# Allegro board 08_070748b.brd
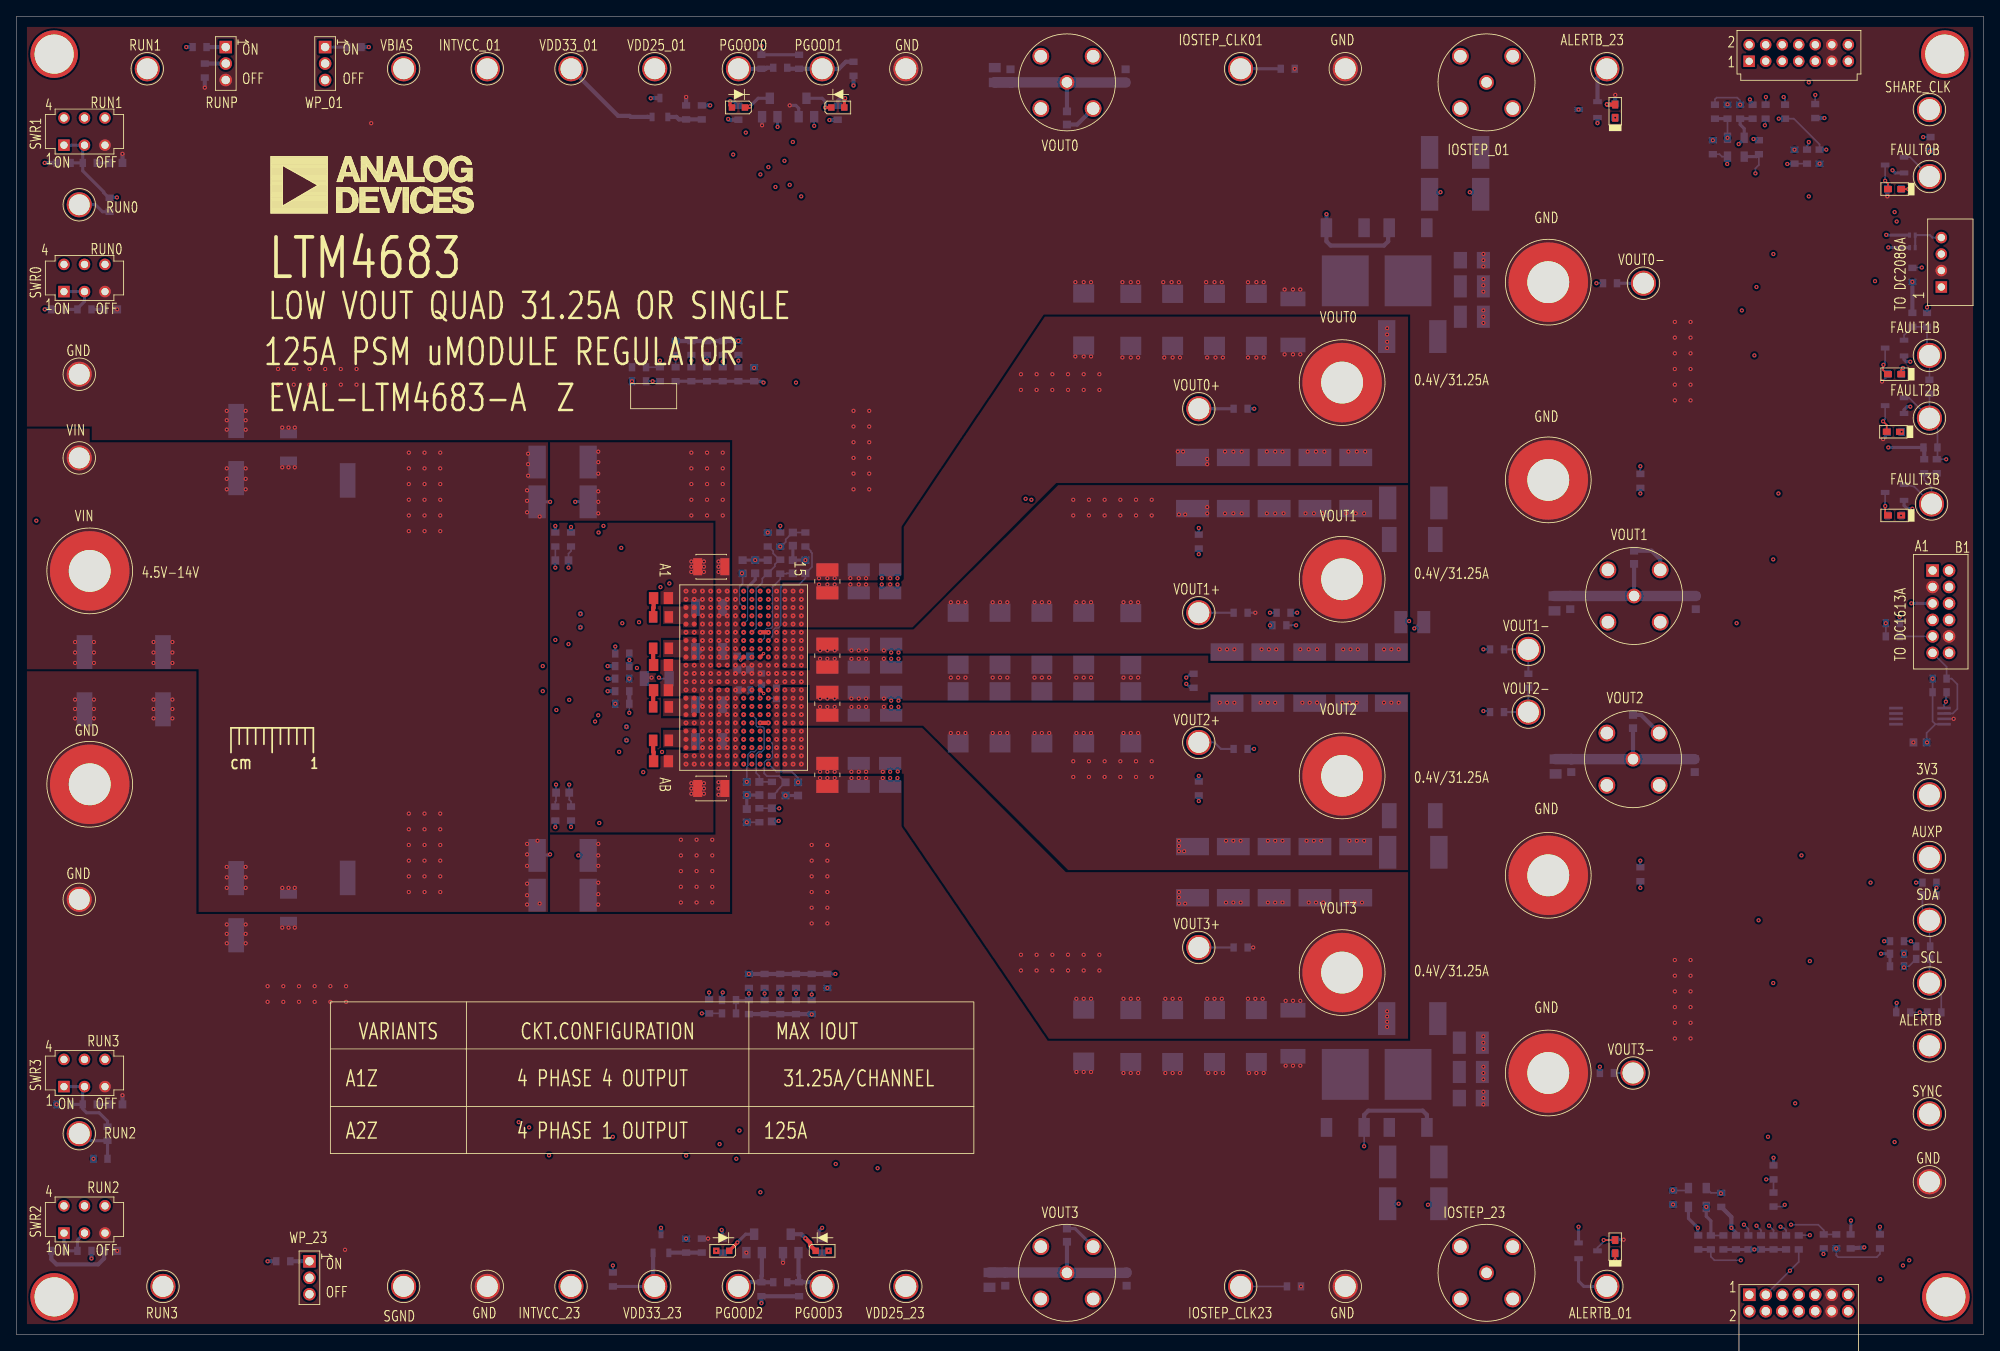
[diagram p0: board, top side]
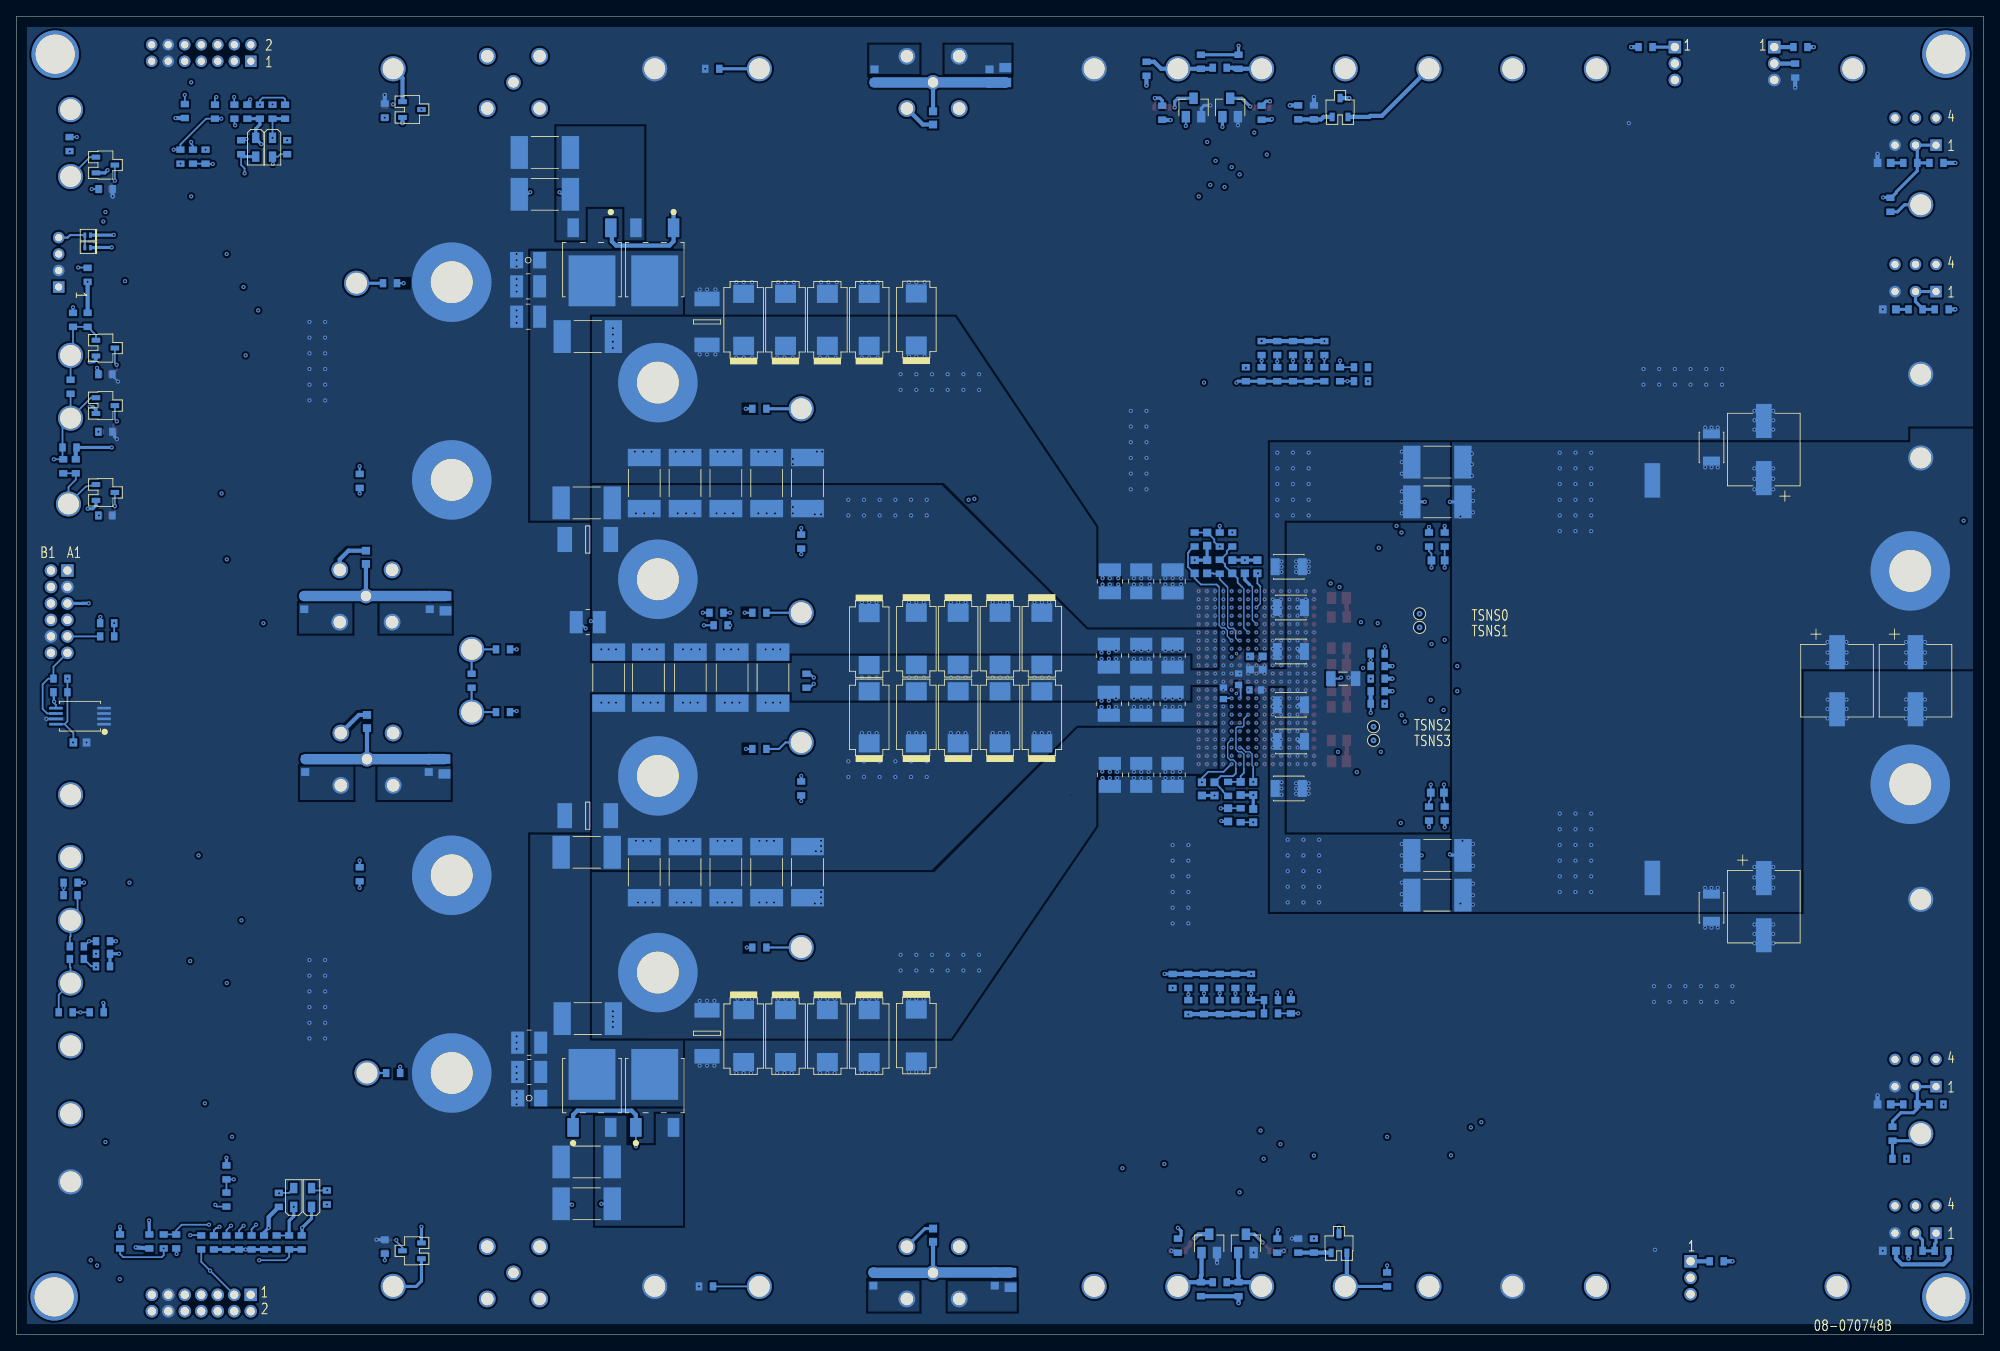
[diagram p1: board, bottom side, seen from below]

Outline 238.76 x 160.02 mm; copper layers: TOP, LAYER_2, LAYER_3, LAYER_4, LAYER_5, LAYER_6, LAYER_7, BOTTOM. Coordinates in mm from the lower left corner of the outline.
Outline path: 0,160.02 0,0 238.76,0 238.76,160.02 0,160.02

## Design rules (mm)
constraint set DEFAULT: min track width 0.203

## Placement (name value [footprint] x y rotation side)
C1  1000pF  [C0603#2]  88.65 62.99 270 bottom
C2  100pF  [C0603#2]  90.17 66.29 90 bottom
C12  TBD0805  [C0805]  78.23 69.6 180 top
C14  0.1uF  [C0603#2]  231.05 71.88 180 bottom
C17  TBD0805  [C0805]  78.23 78.23 180 top
C18  1000pF  [C0603#2]  91.69 63.09 90 bottom
C19  100pF  [C0603#2]  93.34 66.24 90 bottom
C25  1uF  [C0603]  88.39 78.26 0 bottom
C26  2.2uF  [C0603#2]  87.5 81.53 90 bottom
C27  2.2uF  [C0603]  92.26 77.85 270 bottom
C28  TBD0603  [C0603#2]  66.21 93.98 0 bottom
C33  TBD0603  [C0603#2]  66.29 65.79 0 bottom
C38  4.7uF  [C0603#2]  89.03 81.53 90 bottom
C39  1UF  [C0603#2]  89.66 93.22 270 bottom
C40  1UF  [C0603#2]  88.14 93.22 270 bottom
C41  4.7uF  [C0603]  90.42 79.56 270 bottom
C42  1UF  [C0603#2]  88.65 66.29 90 bottom
C43  1UF  [C0603#2]  94.87 66.24 90 bottom
C44  22uF  [C1206]  77.72 79.63 0 bottom
C48  1000pF  [C0603#2]  95.76 93.22 90 bottom
C49  100pF  [C0603#2]  94.23 93.22 90 bottom
C50  1000pF  [C0603#2]  94.23 96.57 270 bottom
C51  100pF  [C0603#2]  91.19 93.22 90 bottom
C55  TBD0805  [C0805]  78.23 89.41 180 top
C56  TBD0805  [C0805]  78.23 81.28 180 top
C65  100uF  [C1206H71]  176.66 130.43 180 bottom
C66  100uF  [C1206H71]  176.53 28.7 180 bottom
C67  100uF  [C1210-2]  176.66 123.57 180 bottom
C68  100uF  [C1210-2]  176.53 35.43 180 bottom
C69  100uF  [C1210-2]  176.66 127.25 180 bottom
C70  100uF  [C1210-2]  176.53 31.88 180 bottom
C71  0.1uF  [C0603#2]  127.51 147.7 270 bottom
C72  0.1uF  [C0603#2]  196.34 94.36 90 bottom
C73  0.1uF  [C0603#2]  196.22 74.42 90 bottom
C74  0.1uF  [C0603#2]  127.51 12.06 90 bottom
C75  0.1uF  [C0603#2]  134.62 152.81 90 bottom
C76  0.1uF  [C0603#2]  188.59 88.86 270 bottom
C77  0.1uF  [C0603#2]  203.71 69.09 270 bottom
C78  0.1uF  [C0603#2]  134.75 6.73 270 bottom
C79  0.1uF  [C0603#2]  120.65 152.81 90 bottom
C80  0.1uF  [C0603#2]  203.83 88.86 270 bottom
C81  0.1uF  [C0603#2]  188.72 69.09 270 bottom
C82  0.1uF  [C0603#2]  120.02 6.73 270 bottom
C84  0.1uF  [C0805]  118.75 152.91 270 bottom
C85  0.1uF  [C0805]  186.69 88.76 90 bottom
C86  0.1uF  [C0805]  186.82 68.96 90 bottom
C87  0.1uF  [C0805]  118.11 6.63 90 bottom
C88  0.01uF  [C0603#2]  11.43 124.46 180 bottom
C89  0.01uF  [C0603#2]  12.06 142.24 180 bottom
C90  0.01uF  [C0603#2]  11.43 10.16 180 bottom
C91  0.01uF  [C0603#2]  12.06 27.94 180 bottom
CIN1  180UF  [CPLSMSQ327H472]  8.25 79.38 270 bottom
CIN2  180UF  [CPLSMSQ327H472]  17.78 79.38 270 bottom
CIN3  180UF  [CPLSMSQ327H472]  26.67 107.44 90 bottom
CIN4  180UF  [CPLSMSQ327H472]  26.67 51.94 270 bottom
CIN5  22uF  [C1210H106]  33.02 107.7 270 bottom
CIN6  22uF  [C1210H106]  33.02 51.82 90 bottom
CIN7  22uF  [C1210H106]  84.33 93.22 0 top
CIN8  22uF  [C1210H106]  84.33 93.22 0 bottom
CIN9  22uF  [C1210H106]  84.07 82.93 0 bottom
CIN10  22uF  [C1210H106]  84.07 88.27 0 bottom
CIN11  22uF  [C1210H106]  84.33 66.29 0 top
CIN12  22uF  [C1210H106]  84.33 66.29 0 bottom
CIN13  22uF  [C1210H106]  84.07 76.45 0 bottom
CIN14  22uF  [C1210H106]  84.07 72.01 0 bottom
CO1  100uF  [C1210-2]  98.42 91.44 270 top
CO2  100uF  [C1210-2]  106.05 91.44 270 bottom
CO3  100uF  [C1210-2]  102.23 91.44 270 bottom
CO4  100uF  [C1210-2]  98.42 91.44 270 bottom
CO5  680UF  [C7343H157]  150.5 123.19 90 bottom
CO6  680UF  [C7343H157]  145.41 123.19 90 bottom
CO7  680UF  [C7343H157]  140.34 123.19 90 bottom
CO8  680UF  [C7343H157]  135.25 123.19 90 bottom
CO9  680UF  [C7343H157]  129.54 123.23 90 bottom
CO10  100uF  [C1210-2]  106.17 82.42 90 bottom
CO11  100uF  [C1210-2]  102.23 82.42 90 bottom
CO12  100uF  [C1210-2]  98.42 82.42 90 top
CO13  100uF  [C1210-2]  98.42 82.42 90 bottom
CO14  680UF  [C7343H157]  114.3 84.47 270 bottom
CO15  680UF  [C7343H157]  119.38 84.47 270 bottom
CO16  680UF  [C7343H157]  124.46 84.47 270 bottom
CO17  680UF  [C7343H157]  129.54 84.47 270 bottom
CO18  680UF  [C7343H157]  135.25 84.43 270 bottom
CO19  100uF  [C1210-2]  98.42 76.58 270 top
CO20  100uF  [C1210-2]  106.17 76.58 270 bottom
CO21  100uF  [C1210-2]  102.23 76.58 270 bottom
CO22  100uF  [C1210-2]  98.42 76.58 270 bottom
CO23  680UF  [C7343H157]  114.3 74.93 90 bottom
CO24  680UF  [C7343H157]  119.38 74.93 90 bottom
CO25  680UF  [C7343H157]  124.46 74.93 90 bottom
CO26  680UF  [C7343H157]  129.54 74.93 90 bottom
CO27  680UF  [C7343H157]  135.25 74.93 90 bottom
CO28  100uF  [C1210-2]  98.42 67.94 90 top
CO29  100uF  [C1210-2]  106.05 67.94 90 bottom
CO30  100uF  [C1210-2]  102.23 67.94 90 bottom
CO31  100uF  [C1210-2]  98.42 67.94 90 bottom
CO32  680UF  [C7343H157]  150.5 36.24 270 bottom
CO33  680UF  [C7343H157]  145.41 36.24 270 bottom
CO34  680UF  [C7343H157]  140.34 36.24 270 bottom
CO35  680UF  [C7343H157]  135.25 36.24 270 bottom
CO36  680UF  [C7343H157]  129.54 36.3 270 bottom
CO37  100uF  [C1210-2]  169.42 86.49 180 bottom
D1  PMEG2005AEL,315  [SOD882]  230.12 133.48 0 bottom
D2  PMEG2005AEL,315  [SOD882]  230.12 131.95 0 bottom
D3  BAV16WS-7-F  [SOD323]  207.68 144.14 270 bottom
D4  BAV16WS-7-F  [SOD323]  209.72 144.14 270 bottom
D5  BAV16WS-7-F  [SOD323]  205.11 16.64 90 bottom
D6  BAV16WS-7-F  [SOD323]  202.95 16.64 90 bottom
DS1  150060GS75000  [LED0603-2]  87.63 148.97 180 top
DS3  150060GS75000  [LED0603-2]  99.69 148.97 0 top
DS4  TLMS1100-GS08  [LED0603]  194.06 148.53 90 top
DS5  150060GS75000  [LED0603-2]  85.72 10.16 180 top
DS6  TLMS1100-GS08  [LED0603]  227.96 139.06 180 top
DS7  150060GS75000  [LED0603-2]  97.79 10.16 0 top
DS8  TLMS1100-GS08  [LED0603]  227.96 116.59 180 top
DS9  TLMS1100-GS08  [LED0603]  194.06 10.67 90 top
DS10  TLMS1100-GS08  [LED0603]  227.81 109.6 180 top
DS11  TLMS1100-GS08  [LED0603]  227.96 99.44 180 top
J1  112404  [CNAMPHENOL112404]  178.44 152.02 0 top
J2  112404  [CNAMPHENOL112404]  178.44 7.49 0 top
J3  112404  [CNAMPHENOL112404]  127.51 152.02 0 top
J4  112404  [CNAMPHENOL112404]  196.34 89.66 0 top
J5  112404  [CNAMPHENOL112404]  196.22 69.85 0 top
J6  112404  [CNAMPHENOL112404]  127.51 7.49 0 top
NOREF  -  []  -215.26 133.35 0 top
NOREF#2  -  [unnamed#2]  234.19 4.57 0 top
NOREF#3  -  []  15.24 301.62 0 top
NOREF#4  -  []  238.76 0 90 top
NOREF#5  -  []  198.75 8.89 270 top
NOREF#6  -  []  0 0 90 top
NOREF#7  -  []  0 0 0 top
NOREF#8  -  []  -222.25 -146.05 0 top
NOREF#9  -  []  9.53 196.6 0 top
NOREF#10  -  []  78.11 197.23 0 top
NOREF#11  -  []  -66.04 -72.39 0 top
NOREF#12  -  []  30.86 130.05 0 top
NOREF#13  -  []  0 160.02 270 top
NOREF#14  -  []  116.84 181.36 0 top
NOREF#15  -  []  -222.25 -146.05 0 top
NOREF#16  -  []  76.2 344.8 0 top
NOREF#17  -  []  141.61 329.56 0 top
NOREF#18  -  [unnamed#2]  4.57 4.57 0 top
NOREF#19  -  [unnamed#2]  234.06 155.45 0 top
NOREF#20  -  []  116.2 199.14 0 top
NOREF#21  -  [unnamed#2]  4.57 155.45 0 top
NOREF#22  -  []  -242.44 -168.4 0 top
NOREF#23  -  []  348.62 318.77 0 top
NOREF#24  -  []  0 160.02 0 top
NOREF#25  -  []  132.72 8.89 0 top
NOREF#26  -  []  238.76 160.02 270 bottom
P1  NRPN031PAEN-RC  [CNTHMHDR1X3L326W79H235]  25.4 156.3 270 top
P2  NRPN031PAEN-RC  [CNTHMHDR1X3L326W79H235]  37.47 156.3 270 top
P3  98414-G06-12ULF  [CNTHMHDR2X6L528W240H244]  232.58 92.76 270 top
P4  NPPN072FJFN-RC  [CNTHFHDRRA2X7L571W283H197]  210.31 156.59 0 top
P5  0877601416  [CNMOLEX0877601416]  210.33 4.83 0 top
P6  DF3A-4P-2DSA  [CNTHMHDR1X4L394W197H209]  233.64 127.18 90 top
P7  5502-14-0034  [CNRDIS5502-14-0034]  74.04 73.79 180 bottom
P8  5502-14-0034  [CNRDIS5502-14-0034]  74.04 72.14 180 bottom
P9  5502-14-0034  [CNRDIS5502-14-0034]  68.45 85.85 180 bottom
P10  5502-14-0034  [CNRDIS5502-14-0034]  68.45 87.5 180 bottom
P17  NRPN031PAEN-RC  [CNTHMHDR1X3L326W79H235]  35.56 8.89 270 top
Q1  SUD50N04-8M8P-4GE3  [TO252-3]  161.29 130.18 0 bottom
Q2  SUD50N04-8M8P-4GE3  [TO252-3]  168.91 29.34 180 bottom
Q3  SUD50N04-8M8P-4GE3  [TO252-3]  168.91 130.18 0 bottom
Q4  SUD50N04-8M8P-4GE3  [TO252-3]  161.29 29.34 180 bottom
Q5  2N7002A-7  [SOT23]  91.44 148.97 180 bottom
Q7  SI2365EDS-T1-GE3  [SOT23_B]  78.11 148.97 180 bottom
Q8  2N7002A-7  [SOT23]  95.89 148.97 180 bottom
Q9  SI2365EDS-T1-GE3  [SOT23_B]  190.75 148.72 270 bottom
Q10  SI2365EDS-T1-GE3  [SOT23_B]  78.23 11.06 180 bottom
Q11  2N7002A-7  [SOT23]  89.53 11.06 180 bottom
Q12  SI2365EDS-T1-GE3  [SOT23_B]  227.96 141.99 270 bottom
Q13  2N7002A-7  [SOT23]  93.98 11.06 180 bottom
Q14  SI2365EDS-T1-GE3  [SOT23_B]  227.96 119.76 270 bottom
Q15  SI2365EDS-T1-GE3  [SOT23_B]  190.75 10.16 90 bottom
Q16  SI2365EDS-T1-GE3  [SOT23_B]  227.96 112.78 270 bottom
Q17  SI2365EDS-T1-GE3  [SOT23_B]  227.96 102.23 270 bottom
R1  10K  [R0603]  231.56 105.41 90 bottom
R2  10K  [R0603]  232.32 107.7 180 bottom
R3  10K  [R0603]  32.38 8.89 180 bottom
R4  10K  [R0603]  72.39 6.69 270 bottom
R5  10K  [R0603]  95 5.5 90 bottom
R6  4.99K  [R0603]  213.27 19.69 90 bottom
R7  10K  [R0603]  90.42 5.5 90 bottom
R8  10  [R0603]  148.59 46.99 180 bottom
R9  10  [R0603]  193.04 31.75 180 bottom
R11  TBD0603  [R0603]  88.9 39.75 90 bottom
R12  TBD0603  [R0603]  90.81 39.75 90 bottom
R13  TBD0603  [R0603]  96.52 39.75 90 bottom
R14  TBD0603  [R0603]  94.61 39.75 90 bottom
R15  TBD0603  [R0603]  92.71 39.75 90 bottom
R16  4.99K  [R0603]  226.19 11.3 90 bottom
R17  10  [R0603]  148.59 71.09 180 bottom
R18  4.99K  [R0603]  233.43 79.63 180 bottom
R19  4.99K  [R0603]  233.43 77.98 180 bottom
R20  10  [R0603]  179.7 75.56 180 bottom
R21  4.99K  [R0603]  229.02 39.12 180 bottom
R22  1.65K  [R0603]  98.42 42.93 90 bottom
R23  TBD0603  [R0603]  88.9 42.93 90 bottom
R24  TBD0603  [R0603]  90.81 42.93 90 bottom
R25  TBD0603  [R0603]  96.52 42.93 90 bottom
R26  TBD0603  [R0603]  94.61 42.93 90 bottom
R27  TBD0603  [R0603]  92.71 42.93 90 bottom
R28  4.99K  [R0603]  228.26 47.75 180 bottom
R29  TBD0805  [R0805]  78.23 72.14 0 top
R30  TBD0805  [R0805]  78.23 76.2 0 top
R31  1  [R0603]  73.53 79.63 180 bottom
R32  1  [R0603]  73.53 81.15 180 bottom
R33  1  [R0603]  73.53 78.11 180 bottom
R34  0  [R0603]  65.41 96.52 90 bottom
R35  0.002  [R2512H35]  66.29 101.09 0 bottom
R36  0.002  [R2512H35]  66.29 105.92 0 bottom
R37  0  [R0603]  67.31 96.52 90 bottom
R38  0  [R0603]  65.41 63.25 270 bottom
R39  0.002  [R2512H35]  66.29 58.17 0 bottom
R40  0.002  [R2512H35]  66.29 53.34 0 bottom
R41  0  [R0603]  67.31 63.25 270 bottom
R42  TBD0805  [R0805]  78.23 87.12 0 top
R43  0  [R0603]  22.22 156.3 180 bottom
R44  TBD0805  [R0805]  78.23 83.31 0 top
R45  787  [R0603]  89.53 116.59 90 bottom
R46  TBD0603  [R0603]  81.92 116.59 90 bottom
R47  TBD0603  [R0603]  80.01 116.59 90 bottom
R48  TBD0603  [R0603]  87.63 116.59 90 bottom
R49  TBD0603  [R0603]  83.82 116.59 90 bottom
R50  TBD0603  [R0603]  85.72 116.59 90 bottom
R51  4.99K  [R0603]  232.2 54.86 180 bottom
R52  TBD0603  [R0603]  22.86 153.46 270 bottom
R53  4.99K  [R0603]  228.26 44.7 180 bottom
R54  TBD0603  [R0603]  84.07 39.84 270 bottom
R55  TBD0603  [R0603]  81.92 119.76 90 bottom
R56  TBD0603  [R0603]  80.01 119.76 90 bottom
R57  TBD0603  [R0603]  87.63 119.76 90 bottom
R58  TBD0603  [R0603]  83.82 119.76 90 bottom
R59  TBD0603  [R0603]  85.72 119.76 90 bottom
R60  4.99K  [R0603]  217.34 143 90 bottom
R61  10  [R0603]  148.59 112.4 180 bottom
R62  10  [R0603]  193.42 127.63 180 bottom
R63  10  [R0603]  148.59 87.63 180 bottom
R64  10  [R0603]  179.7 83.19 180 bottom
R65  4.99K  [R0603]  232.32 144.53 270 bottom
R66  10K  [R0603]  90.42 154.52 90 bottom
R67  10K  [R0603]  95 154.52 90 bottom
R68  10K  [R0603]  228.26 46.23 180 bottom
R69  10K  [R0603]  230.12 128.65 270 bottom
R70  10K  [R0603]  41.02 156.3 0 bottom
R71  10K  [R0603]  230.12 123.19 90 bottom
R72  10K  [R0603]  154.31 153.67 180 bottom
R73  10K  [R0603]  155.07 5.84 180 bottom
R74  0.01  [R2512H35]  174.62 138.43 0 bottom
R75  0.01  [R2512H35]  169.55 15.88 0 bottom
R76  0.01  [R2512H35]  174.62 143.51 0 bottom
R77  0.01  [R2512H35]  169.55 20.95 0 bottom
R78  TBD_SPACER_2512  [R2512]  154.94 122.94 270 bottom
R79  TBD0603  [R0603]  143.51 96.27 270 bottom
R80  TBD0603  [R0603]  197.1 103.63 270 bottom
R81  TBD0603  [R0603]  95.76 96.52 90 bottom
R82  TBD0603  [R0603]  92.71 93.22 90 bottom
R83  TBD0603  [R0603]  92.71 153.8 0 bottom
R84  TBD0603  [R0603]  231.9 123.19 270 bottom
R85  TBD0603  [R0603]  11.3 137.16 90 bottom
R86  TBD2512H35  [R2512H35]  142.75 103.38 270 bottom
R87  TBD2512H35  [R2512H35]  147.7 103.38 270 bottom
R88  TBD2512H35  [R2512H35]  152.65 103.38 270 bottom
R89  TBD2512H35  [R2512H35]  157.61 103.38 270 bottom
R90  TBD2512H35  [R2512H35]  162.56 103.38 270 bottom
R91  TBD_SPACER_2512  [R2512]  169.42 96.52 180 bottom
R92  0  [R2512H35]  169.42 121.16 180 bottom
R93  0  [R2512H35]  169.55 100.97 180 bottom
R94  0  [R2512H35]  169.55 58.55 180 bottom
R95  0  [R2512H35]  169.42 38.35 180 bottom
R96  TBD0603  [R0603]  142.88 79.38 270 bottom
R97  TBD0603  [R0603]  183.51 79.38 270 bottom
R98  TBD0603  [R0603]  92.71 96.52 90 bottom
R99  TBD0603  [R0603]  91.19 96.52 90 bottom
R100  TBD0603  [R0603]  101.6 153.67 270 bottom
R101  TBD0603  [R0603]  232.2 115.06 270 bottom
R102  TBD0603  [R0603]  10.2 21.34 0 bottom
R103  TBD2512H35  [R2512H35]  146.94 79.76 270 bottom
R104  TBD2512H35  [R2512H35]  162.05 79.76 270 bottom
R105  TBD2512H35  [R2512H35]  151.89 79.76 270 bottom
R106  TBD2512H35  [R2512H35]  166.88 79.76 270 bottom
R107  TBD2512H35  [R2512H35]  156.97 79.76 270 bottom
R108  TBD0603  [R0603]  143.51 66.29 270 bottom
R109  TBD0603  [R0603]  197.1 55.88 270 bottom
R110  TBD0603  [R0603]  90.17 63.04 90 bottom
R111  TBD0603  [R0603]  91.69 66.24 270 bottom
R112  TBD0603  [R0603]  92.71 6.35 0 bottom
R113  TBD0603  [R0603]  233.08 105.41 270 bottom
R114  TBD0603  [R0603]  11.05 24.38 90 bottom
R115  TBD_SPACER_2512  [R2512]  169.42 62.99 180 bottom
R116  TBD2512H35  [R2512H35]  162.56 56.13 270 bottom
R117  TBD2512H35  [R2512H35]  152.65 56.13 270 bottom
R118  TBD2512H35  [R2512H35]  147.7 56.13 270 bottom
R119  TBD2512H35  [R2512H35]  142.75 56.13 270 bottom
R120  TBD2512H35  [R2512H35]  157.61 56.13 270 bottom
R121  TBD0603  [R0603]  153.8 87.63 180 bottom
R122  TBD0603  [R0603]  153.29 86.11 180 bottom
R123  TBD_SPACER_2512  [R2512]  154.94 36.58 90 bottom
R124  301  [R0603]  87.63 148.34 270 bottom
R125  TBD0603  [R0603]  75.56 117.44 0 bottom
R126  TBD0603  [R0603]  83.19 148.38 270 bottom
R127  10K  [R0603]  5.08 124.46 180 bottom
R128  TBD0603  [R0603]  81.28 148.38 270 bottom
R129  10  [R0603]  8.25 124.46 180 bottom
R130  301  [R0603]  99.69 148.34 270 bottom
R131  TBD0603  [R0603]  86.49 38.99 0 bottom
R132  TBD0603  [R0603]  81.28 10.8 270 bottom
R133  10K  [R0603]  5.72 142.24 180 bottom
R134  TBD0603  [R0603]  83.19 10.8 270 bottom
R135  10  [R0603]  8.89 142.24 180 bottom
R136  301  [R0603]  85.72 10.8 90.4 bottom
R137  TBD0603  [R0603]  78.11 116.59 270 bottom
R138  10K  [R0603]  8.25 10.16 0 bottom
R139  301  [R0603]  97.79 10.8 90.1 bottom
R140  TBD0603  [R0603]  86.49 40.6 180 bottom
R141  10  [R0603]  5.08 10.16 0 bottom
R142  TBD0603  [R0603]  73.53 82.68 180 bottom
R143  TBD0603  [R0603]  73.53 76.58 180 bottom
R144  301  [R0603]  194.06 10.67 270 bottom
R145  TBD0603  [R0603]  75.56 115.74 180 bottom
R146  10K  [R0603]  5.72 27.94 180 bottom
R147  10  [R0603]  8.89 27.94 180 bottom
R148  0  [R0603]  232.2 53.34 0 bottom
R149  TBD0603  [R0603]  227.75 86.36 180 bottom
R150  TBD0603  [R0603]  227.75 84.76 180 bottom
R151  0  [R0603]  231.43 47.12 180 bottom
R152  0  [R0603]  231.43 45.59 180 bottom
R153  0  [R0603]  232.79 39.12 180 bottom
R154  TBD0603  [R0603]  218.33 148.54 90 bottom
R155  TBD0603  [R0603]  222.63 11.3 270 bottom
R156  0  [R0603]  216.33 11.18 90 bottom
R157  0  [R0603]  212.31 148.46 270 bottom
R158  0  [R0603]  218.86 143 270 bottom
R159  0  [R0603]  213.27 16.38 90 bottom
R160  0  [R0603]  214.67 148.46 270 bottom
R161  0  [R0603]  215.81 143 270 bottom
R162  0  [R0603]  220.89 11.3 270 bottom
R163  TBD0603  [R0603]  219.37 11.3 90 bottom
R164  TBD0603  [R0603]  211.75 11.18 90 bottom
R165  TBD0603  [R0603]  213.27 11.18 90 bottom
R166  TBD0603  [R0603]  214.8 11.18 90 bottom
R167  0  [R0603]  210.22 11.18 270 bottom
R168  TBD0603  [R0603]  209.22 148.46 270 bottom
R169  TBD0603  [R0603]  205.66 11.18 90 bottom
R170  TBD0603  [R0603]  204.14 11.18 90 bottom
R171  0  [R0603]  206.16 148.46 90 bottom
R172  TBD0603  [R0603]  207.68 148.46 270 bottom
R173  TBD0603  [R0603]  210.73 148.46 270 bottom
R174  TBD0603  [R0603]  207.19 11.18 90 bottom
R175  TBD0603  [R0603]  208.71 11.18 90 bottom
R176  TBD0603  [R0603]  205.91 144.14 270 bottom
R177  TBD0603  [R0603]  211.49 144.14 270 bottom
R178  TBD0603  [R0603]  206.92 16.34 90 bottom
R179  TBD0603  [R0603]  201.08 16.64 90 bottom
R180  301  [R0603]  194.06 148.59 270 bottom
R181  301  [R0603]  227.94 139.06 0 bottom
R182  301  [R0603]  227.96 116.59 0 bottom
R183  301  [R0603]  227.96 109.6 0 bottom
R184  301  [R0603]  227.96 99.44 0 bottom
S1  JS202011CQN  [SWTHL354W142H217]  5.77 126.62 0 top
S2  JS202011CQN  [SWTHL354W142H217]  5.77 144.4 0 top
S3  JS202011CQN  [SWTHL354W142H217]  5.77 12.32 0 top
S4  JS202011CQN  [SWTHL354W142H217]  5.77 30.1 0 top
TP1  2501-2-00-80-00-00-07-0  [CNMILLMAX2501]  7.62 106.43 0 top
TP2  2501-2-00-80-00-00-07-0  [CNMILLMAX2501]  161.29 153.67 0 top
TP3  2501-2-00-80-00-00-07-0  [CNMILLMAX2501]  148.59 5.84 0 top
TP4  2501-2-00-80-00-00-07-0  [CNMILLMAX2501]  161.29 5.84 0 top
TP5  CKFH1032-10  [CNCFCKFH1032-10]  160.91 43.94 0 top
TP6  CKFH1032-10  [CNCFCKFH1032-10]  185.93 31.75 0 top
TP7  CKFH1032-10  [CNCFCKFH1032-10]  160.91 67.82 0 top
TP8  CKFH1032-10  [CNCFCKFH1032-10]  185.93 55.75 0 top
TP9  CKFH1032-10  [CNCFCKFH1032-10]  8.89 92.71 0 top
TP10  CKFH1032-10  [CNCFCKFH1032-10]  8.89 66.8 0 top
TP11  2501-2-00-80-00-00-07-0  [CNMILLMAX2501]  7.62 52.83 0 top
TP12  2501-2-00-80-00-00-07-0  [CNMILLMAX2501]  143.51 71.88 0 top
TP13  2501-2-00-80-00-00-07-0  [CNMILLMAX2501]  143.51 46.99 0 top
TP14  2501-2-00-80-00-00-07-0  [CNMILLMAX2501]  183.51 75.56 0 top
TP15  2501-2-00-80-00-00-07-0  [CNMILLMAX2501]  196.22 31.75 0 top
TP16  2501-2-00-80-00-00-07-0  [CNMILLMAX2501]  143.51 112.4 0 top
TP17  2501-2-00-80-00-00-07-0  [CNMILLMAX2501]  197.49 127.63 0 top
TP18  2501-2-00-80-00-00-07-0  [CNMILLMAX2501]  143.51 87.63 0 top
TP19  2501-2-00-80-00-00-07-0  [CNMILLMAX2501]  183.51 83.19 0 top
TP20  CKFH1032-10  [CNCFCKFH1032-10]  160.91 91.69 0 top
TP21  CKFH1032-10  [CNCFCKFH1032-10]  185.93 103.76 0 top
TP22  2501-2-00-80-00-00-07-0  [CNMILLMAX2501]  148.59 153.67 0 top
TP23  CKFH1032-10  [CNCFCKFH1032-10]  160.91 115.57 0 top
TP24  CKFH1032-10  [CNCFCKFH1032-10]  185.93 127.76 0 top
TP25  2501-2-00-80-00-00-07-0  [CNMILLMAX2501]  57.15 153.67 0 top
TP26  2501-2-00-80-00-00-07-0  [CNMILLMAX2501]  67.31 5.84 0 top
TP27  2501-2-00-80-00-00-07-0  [CNMILLMAX2501]  67.31 153.67 0 top
TP28  2501-2-00-80-00-00-07-0  [CNMILLMAX2501]  77.47 5.84 0 top
TP29  2501-2-00-80-00-00-07-0  [CNMILLMAX2501]  77.47 153.67 0 top
TP30  2501-2-00-80-00-00-07-0  [CNMILLMAX2501]  107.95 5.84 0 top
TP31  2501-2-00-80-00-00-07-0  [CNMILLMAX2501]  46.99 153.67 0 top
TP32  2501-2-00-80-00-00-07-0  [CNMILLMAX2501]  7.62 137.16 0 top
TP33  2501-2-00-80-00-00-07-0  [CNMILLMAX2501]  15.88 153.67 0 top
TP34  2501-2-00-80-00-00-07-0  [CNMILLMAX2501]  7.62 24.38 0 top
TP35  2501-2-00-80-00-00-07-0  [CNMILLMAX2501]  17.78 5.84 0 top
TP36  2501-2-00-80-00-00-07-0  [CNMILLMAX2501]  87.63 153.67 0 top
TP37  2501-2-00-80-00-00-07-0  [CNMILLMAX2501]  97.79 153.67 0 top
TP38  2501-2-00-80-00-00-07-0  [CNMILLMAX2501]  87.63 5.84 0 top
TP39  2501-2-00-80-00-00-07-0  [CNMILLMAX2501]  97.79 5.84 0 top
TP40  2501-2-00-80-00-00-07-0  [CNMILLMAX2501]  232.2 140.59 0 top
TP41  2501-2-00-80-00-00-07-0  [CNMILLMAX2501]  232.2 118.87 0 top
TP42  2501-2-00-80-00-00-07-0  [CNMILLMAX2501]  232.2 111.25 0 top
TP43  2501-2-00-80-00-00-07-0  [CNMILLMAX2501]  232.45 100.84 0 top
TP44  2501-2-00-80-00-00-07-0  [CNMILLMAX2501]  193.04 5.84 0 top
TP45  2501-2-00-80-00-00-07-0  [CNMILLMAX2501]  193.04 153.67 0 top
TP46  2501-2-00-80-00-00-07-0  [CNMILLMAX2501]  232.2 65.53 0 top
TP47  2501-2-00-80-00-00-07-0  [CNMILLMAX2501]  232.2 57.91 0 top
TP48  2501-2-00-80-00-00-07-0  [CNMILLMAX2501]  232.2 50.29 0 top
TP49  2501-2-00-80-00-00-07-0  [CNMILLMAX2501]  232.2 42.67 0 top
TP50  2501-2-00-80-00-00-07-0  [CNMILLMAX2501]  232.2 35.05 0 top
TP51  2501-2-00-80-00-00-07-0  [CNMILLMAX2501]  232.2 148.72 0 top
TP52  2501-2-00-80-00-00-07-0  [CNMILLMAX2501]  232.2 26.8 0 top
TP53  2501-2-00-80-00-00-07-0  [CNMILLMAX2501]  46.99 5.84 0 top
TP54  2501-2-00-80-00-00-07-0  [CNMILLMAX2501]  57.15 5.84 0 top
TP55  2501-2-00-80-00-00-07-0  [CNMILLMAX2501]  107.95 153.67 0 top
TP56  2501-2-00-80-00-00-07-0  [CNMILLMAX2501]  7.62 116.59 0 top
TP57  2501-2-00-80-00-00-07-0  [CNMILLMAX2501]  232.2 18.54 0 top
U1  LTM4683  [BGA330_22X15H337]  88.27 79.76 270 top
U3  24LC025-I/ST  [TSSOP8]  231.05 75.07 90 bottom

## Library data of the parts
C1 C18 C48 C50 = CAP: User Part Number: UPN; Tolerance: 5; alternate symbols: (C0603); part number: CAP_SM-1000PF,50V,5,E007908,C0603; tolerance: 5
C2 C19 C49 C51 = CAP: User Part Number: UPN; Tolerance: 1; alternate symbols: (C0603); part number: CAP_SM-100PF,100V,1,E023145,C0603; tolerance: 1
C12 C17 C55 C56 = CAP: User Part Number: UPN; alternate symbols: (C0805); part number: CAP_SM-TBD0805,TBD0805,TBD0805,E000383,C0805
C14 = CAP: User Part Number: UPN; Tolerance: 10; alternate symbols: (C0603); part number: CAP_SM-0.1UF,16V,10,E034157,C0603; tolerance: 10
C25 = CAP: User Part Number: UPN; Tolerance: 10; alternate symbols: (C0603L); part number: CAP_SM-1UF,25V,10,E026591,C0603; tolerance: 10
C26 C27 = CAP: User Part Number: UPN; Tolerance: 10; alternate symbols: (C0603L); part number: CAP_SM-2.2UF,25V,10,E031885,C0603; tolerance: 10
C28 C33 = CAP: User Part Number: UPN; alternate symbols: (C0603); part number: CAP_SM-TBD0603,TBD0603,TBD0603,E000382,C0603
C38 C41 = CAP: User Part Number: UPN; Tolerance: 10; alternate symbols: (C0603L); part number: CAP_SM-4.7UF,16V,10,E022190,C0603; tolerance: 10
C39 C40 C42 C43 = CAP: User Part Number: UPN; Tolerance: 20; alternate symbols: (C0603); part number: CAP_SM-1UF,6.3V,20,E042772,C0603; tolerance: 20
C44 = CAP: User Part Number: UPN; Tolerance: 10; alternate symbols: (C1206); part number: CAP_SM-22UF,16V,10,E026209,C1206; tolerance: 10
C65 C66 = CAP: Tolerance: 10; User Part Number: UPN; alternate symbols: (C1206H71); part number: CAP_SM-100UF,6.3V,10,E039989,C1206H71; tolerance: 10
C67-C70 CO1-CO4 CO10-CO13 CO19-CO22 CO28-CO31 CO37 = CAP: Tolerance: 20; User Part Number: UPN; alternate symbols: (C1210-2); part number: CAP_SM-100UF,6.3V,20,E031805,C1210-2; tolerance: 20
C71-C82 = CAP: User Part Number: UPN; Tolerance: 20; alternate symbols: (C0603); part number: CAP_SM-0.1UF,16V,20,E032308,C0603; tolerance: 20
C84-C87 = CAP: User Part Number: UPN; Tolerance: 20; alternate symbols: (C0805); part number: CAP_SM-0.1UF,16V,20,E042427,C0805; tolerance: 20
C88-C91 = CAP: User Part Number: UPN; Tolerance: 5; alternate symbols: (C0603); part number: CAP_SM-0.01UF,25V,5,E012400,C0603; tolerance: 5
CIN1-CIN4 = CAPP: Tolerance: 20; User Part Number: UPN; alternate symbols: (CPLSMSQ327H472); part number: CAPP_SM-180UF,25V,20,E042361,CPLSMSQ327H472; tolerance: 20
CIN5-CIN14 = CAP: Tolerance: 10; User Part Number: UPN; alternate symbols: (C1210H106); part number: CAP_SM-22UF,25V,10,E025745,C1210H106; tolerance: 10
CO5-CO9 CO14-CO18 CO23-CO27 CO32-CO36 = CAPP: Tolerance: 20; User Part Number: UPN; alternate symbols: (C7343H157); part number: CAPP_SM-680UF,2.5V,20,E057226,C7343H157; tolerance: 20
D1 D2 = DIOSCHOTTKY: Tolerance: N/A; User Part Number: UPN; alternate symbols: (SOD882); part number: DIOSCHOTTKY_SM-PMEG2005AEL,315,20V,N/A,E021538,SOD882; tolerance: N/A
D3-D6 = DIO: Tolerance: N/A; User Part Number: UPN; alternate symbols: (SOD323); part number: DIO_SM-BAV16WS-7-F,75V,N/A,E007349,SOD323; tolerance: N/A
DS1 DS3 DS5 DS7 = DIOLED: Tolerance: N/A; User Part Number: UPN; alternate symbols: (LED0603-2); part number: DIOLED_SM-150060GS75000,3.2V,N/A,E033282,LED0603-2; tolerance: N/A
DS4 DS6 DS8-DS11 = DIOLED: Tolerance: N/A; User Part Number: UPN; alternate symbols: (LED0603); part number: DIOLED_SM-TLMS1100-GS08,N/A,N/A,E015386,LED0603; tolerance: N/A
J1-J6 = CNBNC5P: Tolerance: N/A; User Part Number: UPN; alternate symbols: (CNAMPHENOL112404); part number: CNBNC5P_TH-112404,E020078,CNAMPHENOL112404; tolerance: N/A
P1 P2 P17 = CN3P: Tolerance: N/A; User Part Number: UPN; alternate symbols: (CNTHMHDR1X3L326W79H235); part number: CN3P_TH-NRPN031PAEN-RC,E048452,CNTHMHDR1X3L326W79H235; tolerance: N/A
P3 = CN12P_AB_V2: User Part Number: UPN; Tolerance: N/A; alternate symbols: (CNTHMHDR2X6L528W240H244); part number: CN12P_AB_V2_TH-98414-G06-12ULF,E032251,CNTHMHDR2X6L528W240H244; tolerance: N/A
P4 = CN14P: Tolerance: N/A; User Part Number: UPN; alternate symbols: (CNTHFHDRRA2X7L571W283H197); part number: CN14P_TH-NPPN072FJFN-RC,E053661,CNTHFHDRRA2X7L571W283H197; tolerance: N/A
P5 = CN14P: Tolerance: USD 1.0156; User Part Number: UPN; alternate symbols: (CNMOLEX0877601416); part number: CN14P_TH-0877601416,E052249,CNMOLEX0877601416; tolerance: USD 1.0156
P6 = CN4P: User Part Number: UPN; Tolerance: N/A; alternate symbols: (CNTHMHDR1X4L394W197H209); part number: CN4P_TH-DF3A-4P-2DSA,E050953,CNTHMHDR1X4L394W197H209; tolerance: N/A
P7-P10 = CN1P: User Part Number: UPN; Tolerance: N/A; alternate symbols: (CNRDIS5502-14-0034); part number: CN1P_SM-5502-14-0034,E026616,CNRDIS5502-14-0034; tolerance: N/A
Q1-Q4 = TRANNMOSFET_V8: Tolerance: N/A; User Part Number: UPN; alternate symbols: (TO252-3); part number: TRANNMOSFET_V8_SM-SUD50N04-8M8P-4GE3,E027839,TO252-3; tolerance: N/A
Q5 Q8 Q11 Q13 = TRANNMOSFET_V26: User Part Number: UPN; Tolerance: N/A; alternate symbols: (SOT23); part number: TRANNMOSFET_V26_SM-2N7002A-7,E042602,SOT23; tolerance: N/A
Q7 Q9 Q10 Q12 Q14-Q17 = TRANPMOSFET_V24: User Part Number: UPN; Tolerance: N/A; alternate symbols: (SOT23_B); part number: TRANPMOSFET_V24_SM-SI2365EDS-T1-GE3,E046928,SOT23_B; tolerance: N/A
R1-R5 R7 R66-R73 R127 R133 R138 R146 = RES: User Part Number: UPN; Tolerance: 1; alternate symbols: (R0603); part number: RES_SM-10K,E003671,1/10W,1,R0603; tolerance: 1
R6 R16 R18 R19 R21 R28 R51 R53 R60 R65 = RES: User Part Number: UPN; Tolerance: 1; alternate symbols: (R0603); part number: RES_SM-4.99K,E003726,1/10W,1,R0603; tolerance: 1
R8 R9 R17 R20 R61-R64 R129 R135 R141 R147 = RES: User Part Number: UPN; Tolerance: 0.1; alternate symbols: (R0603); part number: RES_SM-10,E056047,1/16W,0.1,R0603; tolerance: 0.1
R11-R15 R23-R27 R46-R50 R52 R54-R59 R79-R85 R96-R102 R108-R114 R121 R122 R125 R126 R128 R131 R132 R134 R137 R140 R142 R143 R145 R149 R150 R154 R155 R163-R166 R168-R170 R172-R179 = RES: User Part Number: UPN; alternate symbols: (R0603); part number: RES_SM-TBD0603,E004050,TBD0603,TBD0603,R0603
R22 = RES: User Part Number: UPN; Tolerance: 1; alternate symbols: (R0603); part number: RES_SM-1.65K,E042857,1/10W,1,R0603; tolerance: 1
R29 R30 R42 R44 = RES: User Part Number: UPN; alternate symbols: (R0805); part number: RES_SM-TBD0805,E004051,TBD0805,TBD0805,R0805
R31-R33 = RES: User Part Number: UPN; Tolerance: 5; alternate symbols: (R0603); part number: RES_SM-1,E011738,1/10W,5,R0603; tolerance: 5
R34 R37 R38 R41 R43 R148 R151-R153 R156-R162 R167 R171 = RES: User Part Number: UPN; Tolerance: JUMPER; alternate symbols: (R0603); part number: RES_SM-0,E006826,1/10W,JUMPER,R0603; tolerance: JUMPER
R35 R36 R39 R40 = RES: User Part Number: UPN; Tolerance: 1; alternate symbols: (R2512H35); part number: RES_SM-0.002,E020617,1W,1,R2512H35; tolerance: 1
R45 = RES: User Part Number: UPN; Tolerance: 1; alternate symbols: (R0603); part number: RES_SM-787,E028801,1/10W,1,R0603; tolerance: 1
R74-R77 = RES: User Part Number: UPN; Tolerance: 1; alternate symbols: (R2512H35); part number: RES_SM-0.01,E019380,2W,1,R2512H35; tolerance: 1
R78 R91 R115 R123 = RES: Tolerance: N/A; User Part Number: UPN; alternate symbols: (R2512); part number: RES_SM-TBD_SPACER_2512,E011817,N/A,N/A,R2512; tolerance: N/A
R86-R90 R103-R107 R116-R120 = RES: User Part Number: UPN; Tolerance: N/A; alternate symbols: (R2512H35); part number: RES_SM-TBD2512H35,E061126,N/A,N/A,R2512H35; tolerance: N/A
R92-R95 = RES: User Part Number: UPN; Tolerance: JUMPER; alternate symbols: (R2512H35); part number: RES_SM-0,E050944,N/A,JUMPER,R2512H35; tolerance: JUMPER
R124 R130 R136 R139 R144 R180-R184 = RES: User Part Number: UPN; Tolerance: 1; alternate symbols: (R0603); part number: RES_SM-301,E003699,1/10W,1,R0603; tolerance: 1
S1-S4 = SWDPDT_V5: Tolerance: N/A; User Part Number: UPN; alternate symbols: (SWTHL354W142H217); part number: SWDPDT_V5_TH-JS202011CQN,E025828,SWTHL354W142H217; tolerance: N/A
TP1-TP4 TP11-TP19 TP22 TP25-TP57 = CNTP1P: User Part Number: UPN; Tolerance: N/A; alternate symbols: (CNMILLMAX2501); part number: CNTP1P_TH-2501-2-00-80-00-00-07-0,E031108,CNMILLMAX2501; tolerance: N/A
TP5-TP10 TP20 TP21 TP23 TP24 = CNTP1P: Tolerance: N/A; User Part Number: UPN; alternate symbols: (CNCFCKFH1032-10); part number: CNTP1P_TH-CKFH1032-10,E050511,CNCFCKFH1032-10; tolerance: N/A
U1 = ADLTM4683: Tolerance: N/A; User Part Number: UPN; alternate symbols: (BGA330_22X15H337); part number: ADLTM4683_SM-LTM4683,E056547,BGA330_22X15H337; tolerance: N/A
U3 = IC24XX02: Tolerance: N/A; User Part Number: UPN; alternate symbols: (TSSOP8); part number: IC24XX02_SM-24LC025-I/ST,E032095,TSSOP8; tolerance: N/A

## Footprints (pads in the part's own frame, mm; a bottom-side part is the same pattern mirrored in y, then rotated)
BGA330_22X15H337
  round 0.61 smd: A1(-10.5,-7) A2(-10.5,-6) A3(-10.5,-5) A4(-10.5,-4) A5(-10.5,-3) A6(-10.5,-2) A7(-10.5,-1) A8(-10.5,0) A9(-10.5,1) A10(-10.5,2) A11(-10.5,3) A12(-10.5,4) A13(-10.5,5) A14(-10.5,6) A15(-10.5,7) AA1(9.5,-7) AA2(9.5,-6) AA3(9.5,-5) AA4(9.5,-4) AA5(9.5,-3) AA6(9.5,-2) AA7(9.5,-1) AA8(9.5,0) AA9(9.5,1) AA10(9.5,2) AA11(9.5,3) AA12(9.5,4) AA13(9.5,5) AA14(9.5,6) AA15(9.5,7) AB1(10.5,-7) AB2(10.5,-6) AB3(10.5,-5) AB4(10.5,-4) AB5(10.5,-3) AB6(10.5,-2) AB7(10.5,-1) AB8(10.5,0) AB9(10.5,1) AB10(10.5,2) AB11(10.5,3) AB12(10.5,4) AB13(10.5,5) AB14(10.5,6) AB15(10.5,7) B1(-9.5,-7) B2(-9.5,-6) B3(-9.5,-5) B4(-9.5,-4) B5(-9.5,-3) B6(-9.5,-2) B7(-9.5,-1) B8(-9.5,0) B9(-9.5,1) B10(-9.5,2) B11(-9.5,3) B12(-9.5,4) B13(-9.5,5) B14(-9.5,6) B15(-9.5,7) C1(-8.5,-7) C2(-8.5,-6) C3(-8.5,-5) C4(-8.5,-4) C5(-8.5,-3) C6(-8.5,-2) C7(-8.5,-1) C8(-8.5,0) C9(-8.5,1) C10(-8.5,2) C11(-8.5,3) C12(-8.5,4) C13(-8.5,5) C14(-8.5,6) C15(-8.5,7) D1(-7.5,-7) D2(-7.5,-6) D3(-7.5,-5) D4(-7.5,-4) D5(-7.5,-3) D6(-7.5,-2) D7(-7.5,-1) D8(-7.5,0) D9(-7.5,1) D10(-7.5,2) D11(-7.5,3) D12(-7.5,4) D13(-7.5,5) D14(-7.5,6) D15(-7.5,7) E1(-6.5,-7) E2(-6.5,-6) E3(-6.5,-5) E4(-6.5,-4) E5(-6.5,-3) E6(-6.5,-2) E7(-6.5,-1) E8(-6.5,0) E9(-6.5,1) E10(-6.5,2) E11(-6.5,3) E12(-6.5,4) E13(-6.5,5) E14(-6.5,6) E15(-6.5,7) F1(-5.5,-7) F2(-5.5,-6) F3(-5.5,-5) F4(-5.5,-4) F5(-5.5,-3) F6(-5.5,-2) F7(-5.5,-1) F8(-5.5,0) F9(-5.5,1) F10(-5.5,2) F11(-5.5,3) F12(-5.5,4) F13(-5.5,5) F14(-5.5,6) F15(-5.5,7) G1(-4.5,-7) G2(-4.5,-6) G3(-4.5,-5) G4(-4.5,-4) G5(-4.5,-3) G6(-4.5,-2) G7(-4.5,-1) G8(-4.5,0) G9(-4.5,1) G10(-4.5,2) G11(-4.5,3) G12(-4.5,4) G13(-4.5,5) G14(-4.5,6) G15(-4.5,7) H1(-3.5,-7) H2(-3.5,-6) H3(-3.5,-5) H4(-3.5,-4) H5(-3.5,-3) H6(-3.5,-2) H7(-3.5,-1) H8(-3.5,0) H9(-3.5,1) H10(-3.5,2) H11(-3.5,3) H12(-3.5,4) H13(-3.5,5) H14(-3.5,6) H15(-3.5,7) J1(-2.5,-7) J2(-2.5,-6) J3(-2.5,-5) J4(-2.5,-4) J5(-2.5,-3) J6(-2.5,-2) J7(-2.5,-1) J8(-2.5,0) J9(-2.5,1) J10(-2.5,2) J11(-2.5,3) J12(-2.5,4) J13(-2.5,5) J14(-2.5,6) J15(-2.5,7) K1(-1.5,-7) K2(-1.5,-6) K3(-1.5,-5) K4(-1.5,-4) K5(-1.5,-3) K6(-1.5,-2) K7(-1.5,-1) K8(-1.5,0) K9(-1.5,1) K10(-1.5,2) K11(-1.5,3) K12(-1.5,4) K13(-1.5,5) K14(-1.5,6) K15(-1.5,7) L1(-0.5,-7) L2(-0.5,-6) L3(-0.5,-5) L4(-0.5,-4) L5(-0.5,-3) L6(-0.5,-2) L7(-0.5,-1) L8(-0.5,0) L9(-0.5,1) L10(-0.5,2) L11(-0.5,3) L12(-0.5,4) L13(-0.5,5) L14(-0.5,6) L15(-0.5,7) M1(0.5,-7) M2(0.5,-6) M3(0.5,-5) M4(0.5,-4) M5(0.5,-3) M6(0.5,-2) M7(0.5,-1) M8(0.5,0) M9(0.5,1) M10(0.5,2) M11(0.5,3) M12(0.5,4) M13(0.5,5) M14(0.5,6) M15(0.5,7) N1(1.5,-7) N2(1.5,-6) N3(1.5,-5) N4(1.5,-4) N5(1.5,-3) N6(1.5,-2) N7(1.5,-1) N8(1.5,0) N9(1.5,1) N10(1.5,2) N11(1.5,3) N12(1.5,4) N13(1.5,5) N14(1.5,6) N15(1.5,7) P1(2.5,-7) P2(2.5,-6) P3(2.5,-5) P4(2.5,-4) P5(2.5,-3) P6(2.5,-2) P7(2.5,-1) P8(2.5,0) P9(2.5,1) P10(2.5,2) P11(2.5,3) P12(2.5,4) P13(2.5,5) P14(2.5,6) P15(2.5,7) R1(3.5,-7) R2(3.5,-6) R3(3.5,-5) R4(3.5,-4) R5(3.5,-3) R6(3.5,-2) R7(3.5,-1) R8(3.5,0) R9(3.5,1) R10(3.5,2) R11(3.5,3) R12(3.5,4) R13(3.5,5) R14(3.5,6) R15(3.5,7) T1(4.5,-7) T2(4.5,-6) T3(4.5,-5) T4(4.5,-4) T5(4.5,-3) T6(4.5,-2) T7(4.5,-1) T8(4.5,0) T9(4.5,1) T10(4.5,2) T11(4.5,3) T12(4.5,4) T13(4.5,5) T14(4.5,6) T15(4.5,7) U1(5.5,-7) U2(5.5,-6) U3(5.5,-5) U4(5.5,-4) U5(5.5,-3) U6(5.5,-2) U7(5.5,-1) U8(5.5,0) U9(5.5,1) U10(5.5,2) U11(5.5,3) U12(5.5,4) U13(5.5,5) U14(5.5,6) U15(5.5,7) V1(6.5,-7) V2(6.5,-6) V3(6.5,-5) V4(6.5,-4) V5(6.5,-3) V6(6.5,-2) V7(6.5,-1) V8(6.5,0) V9(6.5,1) V10(6.5,2) V11(6.5,3) V12(6.5,4) V13(6.5,5) V14(6.5,6) V15(6.5,7) W1(7.5,-7) W2(7.5,-6) W3(7.5,-5) W4(7.5,-4) W5(7.5,-3) W6(7.5,-2) W7(7.5,-1) W8(7.5,0) W9(7.5,1) W10(7.5,2) W11(7.5,3) W12(7.5,4) W13(7.5,5) W14(7.5,6) W15(7.5,7) Y1(8.5,-7) Y2(8.5,-6) Y3(8.5,-5) Y4(8.5,-4) Y5(8.5,-3) Y6(8.5,-2) Y7(8.5,-1) Y8(8.5,0) Y9(8.5,1) Y10(8.5,2) Y11(8.5,3) Y12(8.5,4) Y13(8.5,5) Y14(8.5,6) Y15(8.5,7)
C0603
  rect 0.762x0.889 smd: 1(-0.7,0) 2(0.7,0)
C0603#2
  rect 0.94x0.991 smd: 1(-0.8,0) 2(0.8,0)
C0805
  rect 1.143x1.448 smd: 1(-0.9,0) 2(0.9,0)
C1206
  rect 1.143x1.803 smd: 1(-1.5,0) 2(1.5,0)
C1206H71
  rect 1.6x2.007 smd: 1(-1.397,0) 2(1.397,0)
C1210-2
  rect 1.575x2.692 smd: 1(-1.397,0) 2(1.397,0)
C1210H106
  rect 1.092x2.057 smd: 1(-1.646,0) 2(1.646,0)
C7343H157
  rect 2.21x2.54 smd: N(3.16,0) P(-3.16,0)
CNAMPHENOL112404
  round 1.778 hole 1.27: 1(0,0)
  round 2.032 hole 1.524: 2(-3.175,3.175) 3(3.175,3.175) 4(3.175,-3.175) 5(-3.175,-3.175)
CNCFCKFH1032-10
  round 9.652 hole 5.08: 1(0,0)
CNMILLMAX2501
  round 3.048 hole 2.54: 1(0,0)
CNMOLEX0877601416
  rect 1.524x1.524 hole 1.016: 1(0,0)
  round 1.524 hole 1.016: 2(0,-2) 3(2,0) 4(2,-2) 5(4,0) 6(4,-2) 7(6,0) 8(6,-2) 9(8,0) 10(8,-2) 11(10,0) 12(10,-2) 13(12,0) 14(12,-2)
CNRDIS5502-14-0034
  round 0.711 smd: 1(0,0)
CNTHFHDRRA2X7L571W283H197
  rect 1.397x1.397 hole 0.889: 1(0,-2.007)
  round 1.397 hole 0.889: 2(0,0) 3(2.007,-2.007) 4(2.007,0) 5(4.013,-2.007) 6(4.013,0) 7(6.02,-2.007) 8(6.02,0) 9(8.026,-2.007) 10(8.026,0) 11(10.033,-2.007) 12(10.033,0) 13(12.04,-2.007) 14(12.04,0)
CNTHMHDR1X3L326W79H235
  rect 1.524x1.524 hole 1.016: 1(0,0)
  round 1.524 hole 1.016: 2(2,0) 3(4,0)
CNTHMHDR1X4L394W197H209
  rect 1.397x1.397 hole 0.889: 1(0,0)
  round 1.397 hole 0.889: 2(2,0) 3(4,0) 4(6,0)
CNTHMHDR2X6L528W240H244
  rect 1.524x1.524 hole 1.016: A1(0,0)
  round 1.524 hole 1.016: A2(2,0) A3(4,0) A4(6,0) A5(8,0) A6(10,0) B1(0,2) B2(2,2) B3(4,2) B4(6,2) B5(8,2) B6(10,2)
CPLSMSQ327H472
  rect 4.14x1.905 smd: N(3.47,0) P(-3.47,0)
LED0603
  rect 0.965x0.762 smd: A(0.8,0) C(-0.8,0)
LED0603-2
  rect 0.787x0.787 smd: A(0.787,0) C(-0.787,0)
R0603
  rect 0.787x0.991 smd: 1(-0.85,0) 2(0.85,0)
R0805
  rect 1.041x1.397 smd: 1(-0.95,0) 2(0.95,0)
R2512
  rect 1.778x3.048 smd: 1(-2.794,0) 2(2.794,0)
R2512H35
  rect 2.108x3.988 smd: 1(-3.104,0) 2(3.104,0)
SOD323
  rect 1.27x0.889 smd: A(1.143,0) C(-1.143,0)
SOD882
  rect 0.356x0.635 smd: A(0.34,0) C(-0.34,0)
SOT23
  rect 1.016x1.397 smd: 1(-0.94,-1.118) 2(0.94,-1.118) 3(0,1.118)
SOT23_B
  rect 0.61x1.041 smd: 1(-0.958,-1.15) 2(0.958,-1.15) 3(0,1.15)
SWTHL354W142H217
  rect 1.397x1.397 hole 0.889: 1(0,0)
  round 1.397 hole 0.889: 2(2.489,0) 3(4.978,0) 4(0,3.302) 5(2.489,3.302) 6(4.978,3.302)
TO252-3
  rect 1.397x2.286 smd: 1(-2.29,-4.191) 2(2.28,-4.191)
  rect 5.69x6.172 smd: 3(0,2.248)
TSSOP8
  rect 0.33x1.651 smd: 1(-0.975,-2.92) 2(-0.325,-2.92) 3(0.325,-2.92) 4(0.975,-2.92) 5(0.975,2.92) 6(0.325,2.92) 7(-0.325,2.92) 8(-0.975,2.92)
unnamed#2
  round 5.766 hole 4.75 unplated: (0,0)

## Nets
3V3: P3.A3 Q7.3 Q9.2(S) Q10.3 Q12.2(S) Q14.2(S) Q15.2(S) Q16.2(S) Q17.2(S) R124.2(N2) R130.2(N2) R136.2(N2) R139.2(N2) R154.1 TP46.1(N1)
AGND: C1.1 C2.1 C18.1 C19.1 C39.1 C40.1 C42.1 C43.1 C48.2(N2) C49.2(N2) C50.2(N2) C51.2(N2) P2.3(N3) P17.3(N3) R22.2(N2) R23.2(N2) R24.2(N2) R25.2(N2) R26.2(N2) R27.2(N2) R45.1 R46.1 R47.1 R48.1 R49.1 R50.1 TP53.1(N1) U1.F10 U1.F11 U1.U10 U1.U11
GND_POWER: C12.1 C14.2(N2) C17.1 C25.1 C26.1 C27.1 C38.1 C41.1 C44.1 C55.1 C56.1 C65.1 C66.1 C67.1 C68.1 C69.1 C70.1 C71.2(N2) C72.2(N2) C73.2(N2) C74.2(N2) C75.2(N2) C76.2(N2) C77.2(N2) C78.2(N2) C79.2(N2) C80.2(N2) C81.2(N2) C82.2(N2) C84.1 C85.1 C86.1 C87.1 C88.1 C89.1 C90.1 C91.1 CIN1.N(N2) CIN2.N(N2) CIN3.N(N2) CIN4.N(N2) CIN5.1 CIN6.1 CIN7.1 CIN8.1 CIN9.1 CIN10.1 CIN11.1 CIN12.1 CIN13.1 CIN14.1 CO1.1 CO2.1 CO3.1 CO4.1 CO5.N(N2) CO6.N(N2) CO7.N(N2) CO8.N(N2) CO9.N(N2) CO10.1 CO11.1 CO12.1 CO13.1 CO14.N(N2) CO15.N(N2) CO16.N(N2) CO17.N(N2) CO18.N(N2) CO19.1 CO20.1 CO21.1 CO22.1 CO23.N(N2) CO24.N(N2) CO25.N(N2) CO26.N(N2) CO27.N(N2) CO28.1 CO29.1 CO30.1 CO31.1 CO32.N(N2) CO33.N(N2) CO34.N(N2) CO35.N(N2) CO36.N(N2) CO37.1 J1.2 J1.3 J1.4 J1.5(SH4) J2.2 J2.3 J2.4 J2.5(SH4) J3.2 J3.3 J3.4 J3.5(SH4) J4.2 J4.3 J4.4 J4.5(SH4) J5.2 J5.3 J5.4 J5.5(SH4) J6.2 J6.3 J6.4 J6.5(SH4) P1.3(N3) P3.A2 P3.B5 P4.11 P4.12 P5.11 P5.12 P6.2 Q5.2(S) Q8.2(S) Q11.2(S) Q13.2(S) R9.2(N2) R20.2(N2) R52.2(N2) R62.2(N2) R64.2(N2) R72.1 R73.1 R74.2(N2) R75.2(N2) R76.2(N2) R77.2(N2) R78.1 R91.1 R115.1 R122.1 R123.1 R128.1 R134.1 R144.1 R180.1 R181.1 R182.1 R183.1 R184.1 S1.3 S2.3 S3.3 S4.3 TP2.1(N1) TP4.1(N1) TP6.1(N1) TP8.1(N1) TP10.1(N1) TP11.1(N1) TP21.1(N1) TP24.1(N1) TP54.1(N1) TP55.1(N1) TP56.1(N1) TP57.1(N1) U1.A1 U1.A2 U1.A3 U1.A4 U1.A7 U1.A12 U1.AA1 U1.AA2 U1.AA3 U1.AA4 U1.AA7 U1.AA12 U1.AB1 U1.AB2 U1.AB3 U1.AB4 U1.AB7 U1.AB12 U1.B1 U1.B2 U1.B3 U1.B4 U1.B7 U1.B12 U1.C3 U1.C4 U1.C7 U1.C12 U1.D3 U1.D4 U1.D7 U1.D12 U1.E3 U1.E4 U1.E7 U1.E12 U1.F1 U1.F2 U1.F3 U1.F4 U1.F7 U1.F12 U1.G3 U1.G4 U1.G7 U1.G12 U1.H3 U1.H4 U1.H7 U1.H12 U1.J3 U1.J4 U1.J7 U1.J12 U1.K1 U1.K2 U1.K3 U1.K4 U1.K7 U1.K8 U1.K9 U1.K10 U1.K11 U1.K12 U1.L1 U1.L2 U1.L3 U1.L4 U1.L5 U1.L6 U1.L7 U1.L8 U1.L9 U1.L10 U1.L11 U1.L12 U1.L13 U1.L14 U1.L15 U1.M1 U1.M2 U1.M3 U1.M4 U1.M5 U1.M6 U1.M7 U1.M8 U1.M9 U1.M10 U1.M11 U1.M12 U1.M13 U1.M14 U1.M15 U1.N1 U1.N2 U1.N3 U1.N4 U1.N7 U1.N8 U1.N12 U1.P3 U1.P4 U1.P7 U1.P12 U1.R3 U1.R4 U1.R7 U1.R12 U1.T3 U1.T4 U1.T7 U1.T12 U1.U1 U1.U2 U1.U3 U1.U4 U1.U7 U1.U12 U1.V3 U1.V4 U1.V7 U1.V12 U1.W3 U1.W4 U1.W7 U1.W12 U1.Y3 U1.Y4 U1.Y7 U1.Y12 U3.1 U3.2 U3.3 U3.4 U3.7(WP)
SVIN_01: C26.2(N2) R32.1 R142.1 U1.J8
SVIN_23: C27.2(N2) R33.1 R143.1 U1.P11
VDD25_01: C40.2(N2) R55.2(N2) R56.2(N2) R57.2(N2) R58.2(N2) R59.2(N2) TP29.1(N1) U1.C8
VDD25_23: C43.2(N2) R11.1 R12.1 R13.1 R14.1 R15.1 TP30.1(N1) U1.AB11
VDD33_01: C39.2(N2) D1.C Q7.2(S) R51.2(N2) R53.2(N2) R60.2(N2) R65.2(N2) R66.2(N2) R67.2(N2) R68.2(N2) R69.2(N2) R70.2(N2) R71.2(N2) R127.2(N2) R133.2(N2) TP27.1(N1) U1.E8
VDD33_23: C42.2(N2) D2.C Q10.2(S) R1.2(N2) R2.2(N2) R3.2(N2) R4.2(N2) R5.1 R6.2(N2) R7.1 R16.2(N2) R21.2(N2) R28.2(N2) R138.2(N2) R146.2(N2) TP28.1(N1) U1.Y10
VIN: CIN1.P CIN2.P CIN3.P CIN4.P CIN5.2(N2) CIN6.2(N2) R31.2(N2) R32.2(N2) R33.2(N2) R34.2(N2) R35.1 R36.1 R38.2(N2) R39.1 R40.1 R43.2(N2) R126.1 R132.1 R155.1 TP1.1(N1) TP9.1(N1)
VIN01: CIN7.2(N2) CIN8.2(N2) CIN9.2(N2) CIN10.2(N2) R35.2(N2) R36.2(N2) R37.2(N2) U1.A5 U1.A6 U1.B5 U1.B6 U1.C5 U1.C6 U1.D5 U1.D6 U1.E5 U1.E6 U1.F5 U1.F6 U1.G5 U1.G6 U1.H5 U1.H6 U1.J5 U1.J6 U1.K5 U1.K6
VIN23: CIN11.2(N2) CIN12.2(N2) CIN13.2(N2) CIN14.2(N2) R39.2(N2) R40.2(N2) R41.2(N2) U1.AA5 U1.AA6 U1.AB5 U1.AB6 U1.N5 U1.N6 U1.P5 U1.P6 U1.R5 U1.R6 U1.T5 U1.T6 U1.U5 U1.U6 U1.V5 U1.V6 U1.W5 U1.W6 U1.Y5 U1.Y6
ALERTB: P3.B3 P4.3 P5.3 R156.1 R157.1 TP50.1(N1)
ALERTB_01: Q15.1 R68.1 R156.2(N2) TP44.1(N1) U1.C11
ALERTB_23: Q9.1 R4.1 R157.2(N2) TP45.1(N1) U1.W8
AUXP: C14.1 P3.A1 P4.8 P5.8 R18.2(N2) R19.2(N2) TP47.1(N1) U3.8
AUXSCL: P3.A6 R18.1 U3.6
AUXSDA: P3.B6(N6) R19.1 U3.5
COMP0A: C48.1 R81.1 U1.G11
COMP0B: C49.1 R82.1 U1.G10
COMP1A: C50.1 R81.2(N2) R98.1 U1.G9
COMP1B: C51.1 R82.2(N2) R99.1 U1.F9
COMP2A: C1.2(N2) R98.2(N2) R110.1 U1.T8
COMP2B: C2.2(N2) R99.2(N2) R111.1 U1.T9
COMP3A: C18.2(N2) R110.2(N2) U1.V11
COMP3B: C19.2(N2) R111.2(N2) U1.W11
FAULT0B: D3.A(P) Q12.1 R69.1 R84.1 R167.1 R176.2(N2) TP40.1(N1) U1.A11
FAULT1B: D4.A(P) Q14.1 R71.1 R84.2(N2) R101.1 R164.2(N2) R177.2(N2) TP41.1(N1) U1.A10
FAULT2B: D5.A(P) Q16.1 R2.1 R101.2(N2) R113.1 R165.2(N2) R178.2(N2) TP42.1(N1) U1.V10
FAULT3B: D6.A(P) Q17.1 R1.1 R113.2(N2) R166.2(N2) R179.2(N2) TP43.1(N1) U1.W10
FAULTB: P4.1 P5.1 R164.1 R165.1 R166.1 R167.2(N2) R172.1 R173.1 R174.1 R175.1
INTVCC_01: C38.2(N2) R142.2(N2) TP25.1(N1) U1.J9
INTVCC_23: C41.2(N2) R143.2(N2) TP26.1(N1) U1.P10
PGOOD0: Q5.1 R66.1 R83.1 TP36.1(N1) U1.H9
PGOOD1: Q8.1 R67.1 R83.2(N2) R100.1 TP37.1(N1) U1.H8
PGOOD2: Q11.1 R7.2(N2) R100.2(N2) R112.1 TP38.1(N1) U1.R10
PGOOD3: Q13.1 R5.2(N2) R112.2(N2) TP39.1(N1) U1.T10
RUN0: D3.C R85.1 R127.1 R129.2(N2) R171.1 R172.2(N2) R177.1 S1.1 S1.2 TP32.1(N1) U1.B10
RUN1: D4.C R85.2(N2) R102.1 R133.1 R135.2(N2) R168.2(N2) R173.2(N2) R176.1 S2.1 S2.2 TP33.1(N1) U1.B11
RUN2: D5.C R102.2(N2) R114.1 R138.1 R141.2(N2) R169.2(N2) R174.2(N2) R179.1 S3.1 S3.2 TP34.1(N1) U1.Y9
RUN3: D6.C R114.2(N2) R146.1 R147.2(N2) R170.2(N2) R175.2(N2) R178.1 S4.1 S4.2 TP35.1(N1) U1.Y8
SCL: P3.B2 P4.6 P5.6 P6.3 R152.1 R153.1 TP49.1(N1)
SCL_01: R53.1 R152.2(N2) U1.D10
SCL_23: R21.1 R153.2(N2) U1.W9
SDA: P3.B1 P4.4 P5.4 P6.1 R148.1 R151.1 TP48.1(N1)
SDA_01: R51.1 R148.2(N2) U1.C10
SDA_23: R28.1 R151.2(N2) U1.V8
SHARE_CLK: R158.1 R159.1 R160.2(N2) TP51.1(N1)
SHARE_CLK_01: R65.1 R158.2(N2) U1.D8
SHARE_CLK_23: R6.1 R159.2(N2) U1.AA11
SYNC: R161.1 R162.1 R163.2(N2) TP52.1(N1)
SYNC_01: R60.1 R161.2(N2) U1.D11
SYNC_23: R16.1 R162.2(N2) U1.V9
UNNAMED_2_ADLTM4683_I1_ASEL01: R45.2(N2) U1.B9
UNNAMED_2_ADLTM4683_I1_ASEL23: R22.1 U1.AA10
UNNAMED_2_ADLTM4683_I1_FSWPH01CFG: R50.2(N2) R59.1 U1.A9
UNNAMED_2_ADLTM4683_I1_FSWPH23CFG: R15.2(N2) R27.1 U1.AA9
UNNAMED_2_ADLTM4683_I1_IIN01: C28.2(N2) R37.1 U1.J10
UNNAMED_2_ADLTM4683_I1_IIN01_1: C28.1 R34.1 U1.H10
UNNAMED_2_ADLTM4683_I1_IIN23: C33.1 R38.1 U1.R9
UNNAMED_2_ADLTM4683_I1_IIN23_1: C33.2(N2) R41.1 U1.P9
UNNAMED_2_ADLTM4683_I1_RUNP: P1.2 R52.1 U1.N11
UNNAMED_2_ADLTM4683_I1_SW01: R42.2(N2) U1.C1 U1.C2 U1.D1 U1.D2 U1.E1 U1.E2
UNNAMED_2_ADLTM4683_I1_SW11: R44.2(N2) U1.G1 U1.G2 U1.H1 U1.H2 U1.J1 U1.J2
UNNAMED_2_ADLTM4683_I1_SW21: R30.2(N2) U1.P1 U1.P2 U1.R1 U1.R2 U1.T1 U1.T2
UNNAMED_2_ADLTM4683_I1_SW31: R29.2(N2) U1.V1 U1.V2 U1.W1 U1.W2 U1.Y1 U1.Y2
UNNAMED_2_ADLTM4683_I1_TSNS0: P10.1(N1) U1.E11
UNNAMED_2_ADLTM4683_I1_TSNS1: P9.1(N1) U1.E10
UNNAMED_2_ADLTM4683_I1_TSNS2: P7.1(N1) U1.U8
UNNAMED_2_ADLTM4683_I1_TSNS3: P8.1(N1) U1.U9
UNNAMED_2_ADLTM4683_I1_VINVBIAS: C25.2(N2) R31.1 U1.N9
UNNAMED_2_ADLTM4683_I1_WP01: P2.2 U1.E9
UNNAMED_2_ADLTM4683_I1_WP23: P17.2 U1.Y11(WP_23)
UNNAMED_2_CAP_I53_N2: C12.2(N2) R29.1
UNNAMED_2_CAP_I70_N2: C17.2(N2) R30.1
UNNAMED_2_CAP_I238_N2: C55.2(N2) R42.1
UNNAMED_2_CAP_I249_N2: C56.2(N2) R44.1
UNNAMED_2_CN3P_I72_N1: P17.1 R3.1
UNNAMED_2_CN3P_I268_N1: P2.1 R70.1
UNNAMED_2_CN3P_I335_N1: P1.1 R43.1
UNNAMED_4_CAP_I295_N2: C65.2(N2) C67.2(N2) C69.2(N2) Q1.3 Q3.3 R92.1 R93.1
UNNAMED_4_CAP_I345_N2: C66.2(N2) C68.2(N2) C70.2(N2) Q2.3 Q4.3 R94.1 R95.1
UNNAMED_4_CAP_I413_N2: C88.2(N2) R129.1
UNNAMED_4_CAP_I415_N2: C89.2(N2) R135.1
UNNAMED_4_CAP_I420_N2: C91.2(N2) R147.1
UNNAMED_4_CAP_I427_N2: C90.2(N2) R141.1
UNNAMED_4_CNBNC5P_I301_CNTR: J1.1 Q1.2(S) Q3.2(S) R74.1 R76.1
UNNAMED_4_CNBNC5P_I354_CNTR: J2.1 Q2.2(S) Q4.2(S) R75.1 R77.1
UNNAMED_4_CNTP1P_I307_N1: Q1.1 Q3.1 R72.2(N2) TP22.1(N1)
UNNAMED_4_CNTP1P_I352_N1: Q2.1 Q4.1 R73.2(N2) TP3.1(N1)
UNNAMED_4_DIOLED_I553_N: DS9.C R144.2(N2)
UNNAMED_4_DIOLED_I553_P: DS9.A(P) Q15.3
UNNAMED_4_DIOLED_I558_N: DS7.C Q13.3
UNNAMED_4_DIOLED_I558_P: DS7.A(P) R139.1
UNNAMED_4_DIOLED_I562_N: DS5.C Q11.3
UNNAMED_4_DIOLED_I562_P: DS5.A(P) R136.1
UNNAMED_4_DIOLED_I566_N: DS3.C Q8.3
UNNAMED_4_DIOLED_I566_P: DS3.A(P) R130.1
UNNAMED_4_DIOLED_I570_N: DS1.C Q5.3
UNNAMED_4_DIOLED_I570_P: DS1.A(P) R124.1
UNNAMED_4_DIOLED_I575_N: DS11.C R184.2(N2)
UNNAMED_4_DIOLED_I575_P: DS11.A(P) Q17.3
UNNAMED_4_DIOLED_I576_N: DS10.C R183.2(N2)
UNNAMED_4_DIOLED_I576_P: DS10.A(P) Q16.3
UNNAMED_4_DIOLED_I577_N: DS8.C R182.2(N2)
UNNAMED_4_DIOLED_I577_P: DS8.A(P) Q14.3
UNNAMED_4_DIOLED_I578_N: DS6.C R181.2(N2)
UNNAMED_4_DIOLED_I578_P: DS6.A(P) Q12.3
UNNAMED_4_DIOLED_I579_N: DS4.C R180.2(N2)
UNNAMED_4_DIOLED_I579_P: DS4.A(P) Q9.3
UNNAMED_4_RES_I402_N2: Q7.1 R126.2(N2) R128.2(N2)
UNNAMED_4_RES_I408_N2: Q10.1 R132.2(N2) R134.2(N2)
UNNAMED_5_CN4P_I53_N4: D1.A(P) D2.A(P) P6.4(N4)
UNNAMED_5_CN12PABV2_I55_N4: P3.B4 R149.1
UNNAMED_5_CN12PABV2_I176_N5: P3.A5 R150.1
UNNAMED_5_CN14P_I156_N2: P4.2 P5.2 R149.2(N2) R150.2(N2) R168.1 R169.1 R170.1 R171.2(N2)
UNNAMED_5_CN14P_I156_N5: P4.5 P5.5 R160.1
UNNAMED_5_CN14P_I156_N7: P4.7 P5.7
UNNAMED_5_CN14P_I156_N9: P4.9(N9) P5.9(N9) R163.1
UNNAMED_5_CN14P_I156_N10: P4.10 P5.10 R154.2(N2)
UNNAMED_5_CN14P_I156_N14: P4.13 P4.14 P5.13 P5.14 R155.2(N2)
VBIAS: C44.2(N2) TP31.1(N1) U1.N10
VOSNS0+: R61.2(N2) R79.1 R121.2(N2) TP16.1(N1) U1.J11
VOSNS0-: R62.1 R80.1 R122.2(N2) TP17.1(N1) U1.H11
VOSNS1+: R63.2(N2) R79.2(N2) R96.1 TP18.1(N1) U1.G8
VOSNS1-: R64.1 R80.2(N2) R97.1 TP19.1(N1) U1.F8
VOSNS2+: R17.2(N2) R96.2(N2) R108.1 TP12.1(N1) U1.P8
VOSNS2-: R20.1 R97.2(N2) R109.1 TP14.1(N1) U1.R8
VOSNS3+: R8.2(N2) R108.2(N2) TP13.1(N1) U1.R11
VOSNS3-: R9.1 R109.2(N2) TP15.1(N1) U1.T11
VOUT0: C71.1 C75.1 C79.1 C84.2(N2) CO1.2(N2) CO2.2(N2) CO3.2(N2) CO4.2(N2) CO5.P CO6.P CO7.P CO8.P CO9.P J3.1 R61.1 R78.2(N2) R86.1 R87.1 R88.1 R89.1 R90.1 R92.2(N2) TP23.1(N1) U1.A13 U1.A14 U1.A15 U1.B13 U1.B14 U1.B15 U1.C13 U1.C14 U1.C15 U1.D13 U1.D14 U1.D15 U1.E13 U1.E14 U1.E15
VOUT0_CFG: R46.2(N2) R54.1 R55.1 U1.A8
VOUT1: C72.1 C76.1 C80.1 C85.2(N2) CO10.2(N2) CO11.2(N2) CO12.2(N2) CO13.2(N2) CO14.P CO15.P CO16.P CO17.P CO18.P CO37.2(N2) J4.1 R63.1 R86.2(N2) R87.2(N2) R88.2(N2) R89.2(N2) R90.2(N2) R91.2(N2) R93.2(N2) R103.1 R104.1 R105.1 R106.1 R107.1 R121.1 TP20.1(N1) U1.F13 U1.F14 U1.F15 U1.G13 U1.G14 U1.G15 U1.H13 U1.H14 U1.H15 U1.J13 U1.J14 U1.J15 U1.K13 U1.K14 U1.K15
VOUT1_CFG: R47.2(N2) R54.2(N2) R56.1 R131.1 U1.B8
VOUT2: C73.1 C77.1 C81.1 C86.2(N2) CO19.2(N2) CO20.2(N2) CO21.2(N2) CO22.2(N2) CO23.P CO24.P CO25.P CO26.P CO27.P J5.1 R17.1 R94.2(N2) R103.2(N2) R104.2(N2) R105.2(N2) R106.2(N2) R107.2(N2) R115.2(N2) R116.1 R117.1 R118.1 R119.1 R120.1 TP7.1(N1) U1.N13 U1.N14 U1.N15 U1.P13 U1.P14 U1.P15 U1.R13 U1.R14 U1.R15 U1.T13 U1.T14 U1.T15 U1.U13 U1.U14 U1.U15
VOUT2_CFG: R11.2(N2) R23.1 R131.2(N2) R140.1 U1.AA8
VOUT3: C74.1 C78.1 C82.1 C87.2(N2) CO28.2(N2) CO29.2(N2) CO30.2(N2) CO31.2(N2) CO32.P CO33.P CO34.P CO35.P CO36.P J6.1 R8.1 R95.2(N2) R116.2(N2) R117.2(N2) R118.2(N2) R119.2(N2) R120.2(N2) R123.2(N2) TP5.1(N1) U1.AA13 U1.AA14 U1.AA15 U1.AB13 U1.AB14 U1.AB15 U1.V13 U1.V14 U1.V15 U1.W13 U1.W14 U1.W15 U1.Y13 U1.Y14 U1.Y15
VOUT3_CFG: R12.2(N2) R24.1 R140.2(N2) U1.AB8
VTRIM0_CFG: R48.2(N2) R57.1 U1.D9
VTRIM1_CFG: R49.2(N2) R58.1 R125.2(N2) R137.1 U1.C9
VTRIM2_CFG: R13.2(N2) R25.1 R137.2(N2) R145.1 U1.AB10
VTRIM3_CFG: R14.2(N2) R26.1 R145.2(N2) U1.AB9
VTRIMO_CFG: R125.1

Pads without a net: P3 A4; S1 4 5 6; S2 4 5 6; S3 4 5 6; S4 4 5 6

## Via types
v1: diameter 0.508, hole 0.254, TOP to BOTTOM, 900 vias
v2: diameter 0.406, hole 0.203, TOP to BOTTOM, 301 vias

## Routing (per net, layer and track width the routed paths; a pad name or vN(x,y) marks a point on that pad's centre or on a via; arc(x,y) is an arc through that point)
3V3: length 473.8
  LAYER_4 w0.381: v1(228.98,8.38) 228.98,35.37 234.11,40.5 234.11,63.61 TP46.1 233.59,66.92 233.59,71.85 230,75.44 v1(230,88.77) 230.12,88.9 v1(230.12,100.26) 230.12,112.4 v1(229.87,112.65) v1(229.87,118.11) 229.87,120.02 230.89,121.03 230.89,128.27 230.5,128.65 230.5,136.4 227.71,139.19 v1(227.71,141.35)
  LAYER_5 w0.381: v1(78.23,12.95) 85.34,12.95 v1(85.6,12.7) 86.3,12.7 86.55,12.95 v1(97.79,12.95) 97.92,13.08 v1(189.6,13.08) 201.17,13.08 203.2,11.05 214.88,11.05 216.55,12.71 217.95,12.71 218.44,12.22 218.44,9.27 219.41,8.31 228.9,8.31 v1(228.98,8.38)
  LAYER_5 w0.508: v1(76.99,150.09) 79.5,147.57 v1(86.38,147.57) 86.51,147.7 98.42,147.7 v1(98.68,147.45) 99.06,147.07 99.07,147.07 120.77,147.07 120.77,147.07 121.16,146.69 132.71,146.69 133.1,147.07 173.09,147.07 173.48,146.69 183.38,146.69 183.77,147.07 v1(191.9,147.07) 191.95,147.03 208.07,147.03 209.04,146.05 216.15,146.05 217.79,147.69 v1(219.44,147.69)
  LAYER_6 w0.508: v1(227.71,141.35) 227.45,141.62 227.45,145.17 224.93,147.69 v1(219.44,147.69)
  BOTTOM w0.381: Q16.2 229.12,112.28 229.49,112.65 v1(229.87,112.65) ; Q15.2 v1(189.6,13.08) ; R136.2 85.72,12.58 v1(85.6,12.7) ; Q17.2 229.12,100.64 229.5,100.26 v1(230.12,100.26) ; v1(230,88.77) 230.7,88.77 230.71,88.76 P3.A3 ; Q12.2 228.03,141.03 v1(227.71,141.35) ; v1(97.79,12.95) 97.4,12.57 97.4,12.03 R139.2 ; Q14.2 229.12,118.36 229.36,118.11 v1(229.87,118.11)
  BOTTOM w0.508: v1(76.99,150.09) 77.01,150.11 77.72,150.11 77.73,150.12 Q7.3 ; v1(98.68,147.45) 99.66,147.45 R130.2 ; R154.1 v1(219.44,147.69) ; Q9.2 v1(191.9,147.07) ; v1(86.38,147.57) 86.47,147.49 R124.2 ; Q10.3 v1(78.23,12.95)
AGND: length 312
  TOP w0.508: v2(90.26,74.26) v2(91.26,74.26) ; v2(90.26,85.26) v2(91.26,85.26)
  LAYER_3 w0.152: v2(91.26,85.26) 91.26,85.01 91.76,84.52 91.76,74.75 v2(91.26,74.26) 90.78,73.77 90.78,68.71
  LAYER_3 w0.203: 90.78,67.97 90.78,68.71
  LAYER_3 w0.381: 90.78,67.97 93.31,65.44 v1(93.34,65.44)
  LAYER_4 w0.152: v2(91.26,85.26) 91.78,85.77 91.78,87.46 92.1,87.77 92.47,87.77 92.78,88.09 92.78,88.46 93.1,88.77 93.47,88.77 93.78,89.09 93.78,90.81
  LAYER_4 w0.203: 93.78,90.81 95.76,92.78 v1(95.76,94.02)
  LAYER_4 w0.381: v1(99.4,43.78) 92.52,50.66 v1(92.52,62.36) 92.52,62.67 93.34,63.5 v1(93.34,65.44) ; v1(94.61,115.57) 97.79,112.4 97.79,96.05 v1(95.76,94.02)
  LAYER_5 w0.381: v1(95.76,94.02) v1(89.66,94.02) 88.18,95.5 v1(73.41,95.5) ; v1(88.65,65.49) 93.3,65.49 v1(93.34,65.44) ; v1(94.61,115.57) v1(90.68,115.57)
  LAYER_6 w0.381: v1(73.41,95.5) 72.77,96.14 72.77,113.92 41.53,145.16 41.53,147.45 37.47,151.51 P2.3 ; v1(88.9,43.78) 88.48,43.78 87.63,42.93 87.63,38.48 73.04,23.89 73.04,23.73 72.66,23.36 72.5,23.36 61.09,11.94 34.54,11.94 32.77,10.16 32.77,5.46 33.4,4.83 35.5,4.83 P17.3 46.04,4.89 TP53.1
  BOTTOM w0.381: v1(93.34,65.44) C43.1 ; C40.1 v1(89.66,94.02) C51.2 ; C2.1 v1(88.65,65.49) C1.1 ; C50.2 C49.2 v1(95.76,94.02) ; C18.1 92.45,62.29 v1(92.52,62.36) ; R47.1 R46.1 R49.1 R50.1 R48.1 R45.1 90.51,115.74 v1(90.68,115.57) ; R22.2 v1(99.4,43.78)
  BOTTOM w0.508: v1(88.9,43.78) R24.2 R27.2 R26.2 R25.2 R22.2
